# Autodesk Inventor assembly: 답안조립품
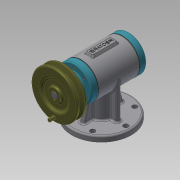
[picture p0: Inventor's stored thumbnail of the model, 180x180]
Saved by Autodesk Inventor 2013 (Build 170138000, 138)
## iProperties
Created: 2019-11
Part Number: 답안조립품
Document SubType Name: Assembly
Designer: Administrator
Mass: 1930.42 g
Surface Area: 1488.57 cm^2
Volume: 478.682 cm^3
Density: 4.03279 g/cm^3
Author: Administrator
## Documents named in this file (18)
- C:\Users\Administrator\Desktop\391104V1056\답안조립품.iam
- C:\Users\Administrator\Desktop\391104V1056\본체.ipt
- C:\Users\Administrator\Desktop\391104V1056\V-벨트풀리.ipt
- C:\Users\Administrator\Desktop\391104V1056\개스킷.ipt
- C:\Users\Administrator\Desktop\391104V1056\뒤커버.ipt
- C:\Users\Administrator\Desktop\391104V1056\멈춤나사 M3x8.ipt
- C:\Users\Administrator\Desktop\391104V1056\베어링 6201.ipt
- C:\Users\Administrator\Desktop\391104V1056\베어링 6202.ipt
- C:\Users\Administrator\Desktop\391104V1056\본체커버.ipt
- C:\Users\Administrator\Desktop\391104V1056\볼트 M3x0.5x8.ipt
- C:\Users\Administrator\Desktop\391104V1056\슬라이드.ipt
- C:\Users\Administrator\Desktop\391104V1056\앞커버.ipt
- C:\Users\Administrator\Desktop\391104V1056\오일 실 12 22 7.ipt
- 오일 실 12 22 7.ipt
- C:\Users\Administrator\Desktop\391104V1056\키 4x4x18.ipt
- 키 4x4x18.ipt
- C:\Users\Administrator\Desktop\391104V1056\편심축.ipt
- C:\Users\Administrator\Desktop\391104V1056\가변스프링.ipt
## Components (4 placed, 3 different names)
1. V-벨트풀리:1
2. 개스킷:1
3. 개스킷:2
4. 가변스프링:1
